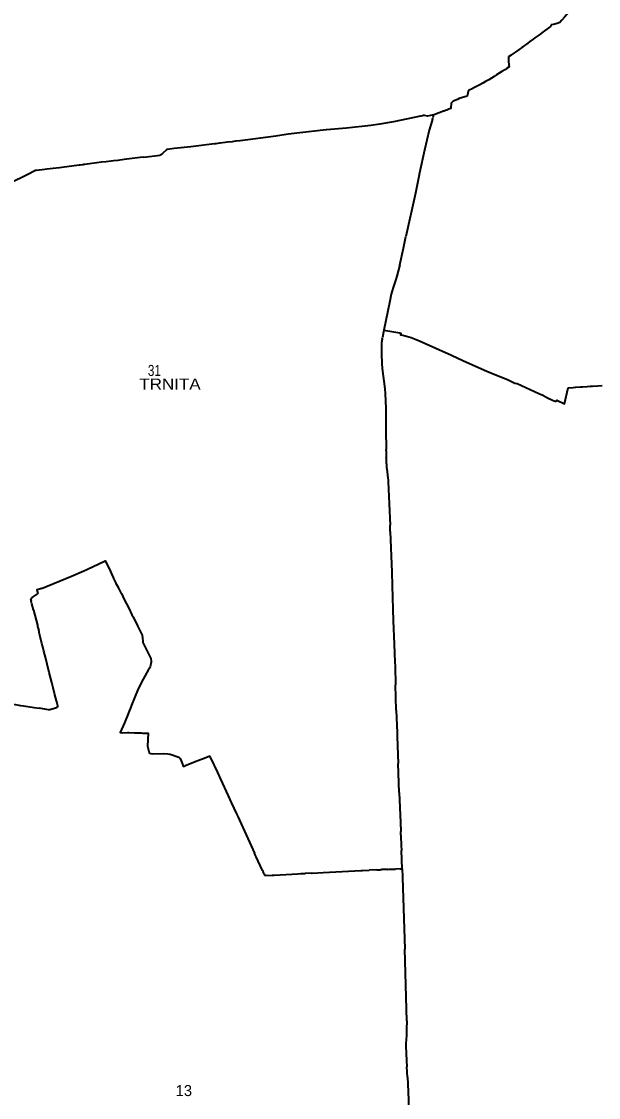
# Model space of a CAD drawing. Extents: x -610940 to -588976, y -1170376 to -1149800.
# Drawn here: x -597562 to -596255, y -1163066 to -1160628 of the extents above; entities that cross this region are included whole.
import ezdxf

# ---------------------------------------------------------------- set-up
doc = ezdxf.new("R2010")
doc.units = 0
doc.header["$LTSCALE"] = 10
doc.layers.add('54', color=7, linetype='Continuous', lineweight=35)
doc.layers.add('55', color=7, linetype='Continuous')
doc.layers.add('56', color=7, linetype='Continuous')

msp = doc.modelspace()

# ---------------------------------------------------------------- linework, layer by layer
at = {"layer": '54'}
for p, q in [((-596361.28, -1160635.63), (-596361.99, -1160635.71)), ((-596342.19, -1160630.16), (-596348.88, -1160632.08)), ((-596549.86, -1160786.62), (-596551.88, -1160794.07)), ((-596549.27, -1160784.45), (-596549.86, -1160786.62)), ((-596653.52, -1160841.44), (-596657.58, -1160842.3)), ((-596651.02, -1160840.91), (-596653.52, -1160841.44)), ((-596649.35, -1160841.13), (-596651.02, -1160840.91)), ((-596629.34, -1160842.41), (-596630.18, -1160846.51)), ((-596628.71, -1160839.33), (-596629.34, -1160842.41)), ((-596630.71, -1160849.11), (-596630.18, -1160846.51)), ((-597095.22, -1160901.65), (-597101.19, -1160902.39)), ((-597344.05, -1160942.66), (-597353.57, -1160943.83)), ((-597329.61, -1160940.82), (-597344.05, -1160942.66)), ((-597285.15, -1160935.22), (-597248.33, -1160930.49)), ((-597246.47, -1160930.25), (-597248.33, -1160930.49)), ((-597242.46, -1160926.68), (-597246.47, -1160930.25)), ((-597430.07, -1160953.25), (-597431.51, -1160953.45)), ((-597429.53, -1160953.19), (-597430.07, -1160953.25)), ((-597422.86, -1160952.37), (-597424.11, -1160952.5)), ((-597380.73, -1160947.01), (-597418.6, -1160951.76)), ((-596669.78, -1161016.63), (-596691.08, -1161114.91)), ((-596704.9, -1161179.49), (-596712.1, -1161204.78)), ((-596741.69, -1161331.15), (-596744.05, -1161344.13)), ((-596741.16, -1161327.91), (-596741.69, -1161331.15)), ((-596741.04, -1161327.3), (-596741.16, -1161327.91)), ((-596744.68, -1161347.37), (-596744.73, -1161347.87)), ((-596744.68, -1161347.37), (-596744.05, -1161344.13)), ((-596736.84, -1161553.27), (-596736, -1161597.69)), ((-596735.95, -1161600.55), (-596736, -1161597.69)), ((-596735.95, -1161600.55), (-596735.93, -1161601.5)), ((-596735.93, -1161601.5), (-596735.66, -1161615.65)), ((-596735.66, -1161615.65), (-596735.64, -1161616.8)), ((-596735.59, -1161619.36), (-596735.64, -1161616.8)), ((-596735.38, -1161630.53), (-596735.59, -1161619.36)), ((-596735.38, -1161630.53), (-596734.96, -1161638.39)), ((-596734.96, -1161638.39), (-596734, -1161646.52)), ((-596734, -1161646.52), (-596732.79, -1161656.86)), ((-596732.79, -1161656.86), (-596731.58, -1161667.09)), ((-596731.58, -1161667.09), (-596731.15, -1161671.05)), ((-596731.15, -1161671.05), (-596729.14, -1161720.69)), ((-596729.14, -1161720.69), (-596726.94, -1161769.42)), ((-596726.66, -1161776.25), (-596726.94, -1161769.42)), ((-596726.61, -1161783.25), (-596726.66, -1161776.25)), ((-597358.38, -1161879.53), (-597354.88, -1161888.15)), ((-597538.25, -1161933.34), (-597542.12, -1161935.99)), ((-597542.12, -1161935.99), (-597540.56, -1161941.62)), ((-597539.06, -1161947.32), (-597540.56, -1161941.62)), ((-597538.25, -1161933.34), (-597528.96, -1161927.14)), ((-597528.96, -1161927.14), (-597528.47, -1161926.81)), ((-597528.47, -1161926.81), (-597527.22, -1161925.96)), ((-597525.1, -1161924.64), (-597527.22, -1161925.96)), ((-597525.1, -1161924.64), (-597525.22, -1161924.16)), ((-597525.77, -1161998.84), (-597523.35, -1162008.25)), ((-597298.72, -1161999.13), (-597298.4, -1161999.66)), ((-597298.02, -1162000.43), (-597298.4, -1161999.66)), ((-596716.06, -1162079.53), (-596715.95, -1162089.1)), ((-596715.95, -1162089.1), (-596714.65, -1162131.42)), ((-596713.28, -1162188.56), (-596714.65, -1162131.42)), ((-597558.11, -1162178.77), (-597533.31, -1162182.49)), ((-597533.31, -1162182.49), (-597522.35, -1162184.25)), ((-597501.5, -1162187.63), (-597522.35, -1162184.25)), ((-597501.5, -1162187.63), (-597481.92, -1162182.56)), ((-597479.8, -1162178.77), (-597481.92, -1162182.56)), ((-596711.1, -1162248.32), (-596708.84, -1162309.27)), ((-597134.47, -1162294.72), (-597126.42, -1162312.09)), ((-596706.41, -1162374.8), (-596708.84, -1162309.27)), ((-597111.13, -1162345.14), (-597094.07, -1162382.32)), ((-596706.41, -1162374.8), (-596703.87, -1162442.68)), ((-597072.18, -1162429.75), (-597034.4, -1162512.2)), ((-596703.87, -1162442.68), (-596703.1, -1162463.36)), ((-596702.78, -1162471.89), (-596703.1, -1162463.36)), ((-596702.03, -1162494.36), (-596701.61, -1162506.82)), ((-597032.55, -1162516.25), (-597034.4, -1162512.2)), ((-597016.3, -1162551.58), (-597030.44, -1162520.85)), ((-596699.58, -1162547.91), (-596701.61, -1162506.82)), ((-597016.3, -1162551.58), (-597014.78, -1162554.89)), ((-596878.48, -1162556.35), (-596792.51, -1162552.05)), ((-596757.26, -1162550.29), (-596774.63, -1162551.16)), ((-596747.82, -1162549.89), (-596746.18, -1162549.82)), ((-596741.73, -1162549.64), (-596746.18, -1162549.82)), ((-596704.56, -1162548.11), (-596701.08, -1162547.97)), ((-597012.75, -1162559.1), (-597014.78, -1162554.89)), ((-597012.75, -1162559.1), (-597010.84, -1162563.09)), ((-596929.62, -1162558.98), (-596919.66, -1162558.45)), ((-596905.17, -1162557.68), (-596919.66, -1162558.45)), ((-596698.99, -1162567.87), (-596693.9, -1162730.32)), ((-596688.82, -1162892.78), (-596693.9, -1162730.32)), ((-596690.16, -1162918.17), (-596690.27, -1162920.56)), ((-596689.27, -1162993.91), (-596689.11, -1162996.91)), ((-596687.89, -1163020.33), (-596689.11, -1162996.91))]:
    msp.add_line(p, q, dxfattribs=at)
for points in [[(-596273.44, -1160540.25), (-596280.42, -1160550.29), (-596285.02, -1160556.87), (-596289.47, -1160563.29), (-596294.15, -1160569.86), (-596298.2, -1160575.35), (-596298.34, -1160575.47), (-596307.24, -1160587.24), (-596307.28, -1160587.47), (-596312.88, -1160594.71), (-596318.4, -1160601.79), (-596322.81, -1160607.17), (-596327.36, -1160612.51), (-596332, -1160618.07), (-596337.97, -1160625.19), (-596342.19, -1160630.16)], [(-596363.49, -1160639.52), (-596376.84, -1160649.22), (-596389.88, -1160658.69), (-596394.39, -1160661.82), (-596398.9, -1160665.06), (-596403.06, -1160668.22), (-596410.31, -1160673.34), (-596415.23, -1160676.89), (-596427.48, -1160685.8), (-596427.33, -1160686.03), (-596431.6, -1160688.94), (-596434.56, -1160691.1)], [(-596363.49, -1160639.52), (-596362.24, -1160637.69), (-596361.99, -1160635.71)], [(-596348.88, -1160632.08), (-596356.69, -1160634.32), (-596361.28, -1160635.63)], [(-596442.11, -1160696.63), (-596446.73, -1160700), (-596446.87, -1160699.81), (-596451.1, -1160702.94), (-596453.08, -1160704.27), (-596458.76, -1160708.19), (-596458.95, -1160719.17), (-596457.08, -1160730.97), (-596463.03, -1160734.71), (-596463.27, -1160734.86), (-596465.86, -1160736.49), (-596473.92, -1160741.47)], [(-596434.56, -1160691.1), (-596439.68, -1160694.85), (-596442.11, -1160696.63)], [(-596473.92, -1160741.47), (-596479.64, -1160745.04), (-596485.69, -1160748.8), (-596491.58, -1160752.5), (-596497.5, -1160756.19), (-596503.44, -1160759.91), (-596510.64, -1160763.95), (-596517.07, -1160767.52), (-596523.55, -1160771.04), (-596529.92, -1160774.55), (-596532.83, -1160775.99), (-596533.05, -1160776.13), (-596537.44, -1160778.4), (-596537.62, -1160778.49), (-596539.2, -1160779.31), (-596539.34, -1160779.4), (-596549.27, -1160784.45)], [(-596551.88, -1160794.07), (-596552.67, -1160796.97), (-596570.65, -1160802.66), (-596574.49, -1160804.27), (-596584.54, -1160808.55), (-596588.55, -1160812.89), (-596589.62, -1160824.14), (-596589.66, -1160824.73), (-596591.97, -1160825.69), (-596594.07, -1160826.58), (-596598.82, -1160828.53)], [(-596657.58, -1160842.3), (-596658.38, -1160842.48), (-596719.45, -1160855.41), (-596750.27, -1160860.4), (-596770.97, -1160863.76), (-596826.22, -1160869.66), (-596871.31, -1160873.02)], [(-596628.71, -1160839.33), (-596642.69, -1160842.03), (-596649.35, -1160841.13)], [(-596598.82, -1160828.53), (-596601.29, -1160829.51), (-596602.89, -1160830.15), (-596605.58, -1160831.19), (-596605.93, -1160831.31), (-596625.66, -1160838.28), (-596628.71, -1160839.33)], [(-596630.71, -1160849.11), (-596632.46, -1160854.62), (-596638.37, -1160874.28), (-596649.21, -1160919.58)], [(-596985.99, -1160887.82), (-597066.88, -1160898.06), (-597067.28, -1160898.11), (-597076.62, -1160899.3), (-597077.47, -1160899.41), (-597085.01, -1160900.36), (-597095.22, -1160901.65)], [(-596871.31, -1160873.02), (-596872.08, -1160873.16), (-596958.3, -1160883), (-596985.99, -1160887.82)], [(-597124.79, -1160905.4), (-597130.84, -1160906.04), (-597178.59, -1160911.56), (-597216.33, -1160915.91), (-597231.99, -1160917.64), (-597233.92, -1160919.06)], [(-597123.81, -1160905.18), (-597124.23, -1160905.27), (-597124.79, -1160905.4)], [(-597122.42, -1160905.11), (-597123.74, -1160905.18), (-597123.81, -1160905.18)], [(-597113.61, -1160903.94), (-597122.33, -1160905.1), (-597122.42, -1160905.11)], [(-597101.19, -1160902.39), (-597112.43, -1160903.79), (-597113.61, -1160903.94)], [(-597285.15, -1160935.22), (-597293.74, -1160936.3), (-597329.61, -1160940.82)], [(-597233.92, -1160919.06), (-597242.16, -1160926.41), (-597242.46, -1160926.68)], [(-596649.21, -1160919.58), (-596660.1, -1160970.96), (-596661.79, -1160978.91), (-596669.78, -1161016.63)], [(-597590.45, -1160994.53), (-597577.12, -1160988.21), (-597560.42, -1160980.25), (-597543.22, -1160971.24), (-597536.36, -1160967.58), (-597532.3, -1160965.69)], [(-597476.58, -1160959.36), (-597504.71, -1160962.66), (-597509.34, -1160963.26), (-597528.56, -1160965.5), (-597532.3, -1160965.69)], [(-597431.51, -1160953.45), (-597470.84, -1160958.68), (-597476.58, -1160959.36)], [(-597424.11, -1160952.5), (-597429.23, -1160953.15), (-597429.53, -1160953.19)], [(-597418.6, -1160951.76), (-597420.83, -1160952.08), (-597422.86, -1160952.37)], [(-597353.57, -1160943.83), (-597370.59, -1160945.89), (-597380.73, -1160947.01)], [(-596704.9, -1161179.49), (-596696.78, -1161141.55), (-596691.08, -1161114.91)], [(-596712.1, -1161204.78), (-596714.44, -1161212.35), (-596720.29, -1161230.91), (-596724.44, -1161246.05), (-596728.04, -1161261.46), (-596741.04, -1161327.3)], [(-596741.04, -1161327.3), (-596731.98, -1161328.97), (-596714.26, -1161332.11), (-596705.03, -1161333.75), (-596702.54, -1161334.46), (-596702.87, -1161334.78), (-596703.35, -1161338.2), (-596701.55, -1161338.23), (-596689.8, -1161341.06), (-596679.19, -1161344.05), (-596667.95, -1161348.36), (-596659.24, -1161352.07), (-596588.24, -1161384.15), (-596560.6, -1161396.67), (-596508.02, -1161420.1), (-596485.72, -1161429.47), (-596461.28, -1161439.53), (-596444.68, -1161447.71), (-596439.34, -1161448.58), (-596389.92, -1161470.85), (-596380.96, -1161475.01), (-596370.62, -1161480.67), (-596359.44, -1161486.25), (-596355.3, -1161487.71), (-596353.09, -1161488.27), (-596351.09, -1161488.44), (-596349.56, -1161486.04), (-596331.58, -1161494.53), (-596323.59, -1161457.84), (-596312.17, -1161457.1), (-596308.04, -1161456.77), (-596306.02, -1161456.62), (-596295.96, -1161455.84), (-596290.88, -1161455.48), (-596280.17, -1161454.72), (-596273.93, -1161454.35), (-596268.35, -1161454), (-596256.72, -1161453.27), (-596246.35, -1161452.65)], [(-596744.73, -1161347.87), (-596746.21, -1161356.03), (-596746.37, -1161381.07), (-596745.69, -1161402.78), (-596744.74, -1161414.35), (-596739.27, -1161460.47), (-596738.61, -1161470.94)], [(-596738.61, -1161470.94), (-596736.51, -1161504.88), (-596736.69, -1161524.12), (-596736.84, -1161553.27)], [(-596726.61, -1161783.25), (-596723.4, -1161875.86), (-596722.33, -1161905.72)], [(-597517.28, -1161913.01), (-597448.65, -1161884.7), (-597421.25, -1161872.96), (-597414.17, -1161869.93), (-597387.09, -1161856.76), (-597386.79, -1161857.17), (-597372.84, -1161850.19), (-597363.22, -1161869.26), (-597358.38, -1161879.53)], [(-597354.88, -1161888.15), (-597353.75, -1161889.76), (-597348.87, -1161900.68)], [(-597517.28, -1161913.01), (-597526.91, -1161915.78), (-597527.28, -1161915.92), (-597525.22, -1161924.16)], [(-597343.83, -1161908.13), (-597344.92, -1161906.51), (-597348.87, -1161900.68)], [(-597336.02, -1161923.91), (-597342.06, -1161911.72), (-597343.83, -1161908.13)], [(-596722.33, -1161905.72), (-596720.01, -1161986.11), (-596717.78, -1162039.3), (-596716.06, -1162079.53)], [(-597336.02, -1161923.91), (-597329.36, -1161937.5), (-597319.47, -1161957.04), (-597312, -1161972.51), (-597309.6, -1161977.35), (-597298.72, -1161999.13)], [(-597535.2, -1161962.02), (-597535.43, -1161961.1), (-597539.06, -1161947.32)], [(-597535.2, -1161962.02), (-597526.44, -1161996.22), (-597525.77, -1161998.84)], [(-597516.67, -1162034.55), (-597520.8, -1162018.57), (-597522.28, -1162012.48), (-597522.61, -1162011.22), (-597523.35, -1162008.25)], [(-597298.02, -1162000.43), (-597288.76, -1162018.65), (-597288.37, -1162025.29), (-597287.64, -1162031.73), (-597287.29, -1162034.8), (-597276.19, -1162057.49), (-597269.53, -1162071.28), (-597269.44, -1162071.87), (-597268.72, -1162076.44), (-597268.58, -1162079.8), (-597271.13, -1162090.53), (-597272.4, -1162093.22), (-597274.27, -1162096.3), (-597283.2, -1162111.65), (-597286.96, -1162118.14), (-597297.95, -1162140.24), (-597299.45, -1162144.1), (-597299.69, -1162143.99), (-597304.9, -1162156.61), (-597304.67, -1162156.66), (-597306.21, -1162160.49), (-597306.53, -1162160.42), (-597313.06, -1162177), (-597312.85, -1162177.03), (-597314.68, -1162181.37), (-597319.99, -1162194.56), (-597320.96, -1162196.92), (-597329.13, -1162216.89), (-597338.37, -1162239.47), (-597334.27, -1162239.52), (-597322.33, -1162239.46), (-597318.93, -1162239.22), (-597306.14, -1162239.86), (-597304.09, -1162239.89), (-597291.25, -1162240.18), (-597288.16, -1162240.29), (-597284.52, -1162240.36), (-597279.62, -1162240.54), (-597275.27, -1162240.6), (-597277.1, -1162270.09)], [(-597513.91, -1162045.29), (-597516.03, -1162037.66), (-597516.67, -1162034.55)], [(-597493.62, -1162125.51), (-597499.33, -1162103.37), (-597504.07, -1162084.57), (-597507.21, -1162071.66), (-597511.52, -1162054.75), (-597513.91, -1162045.29)], [(-597479.8, -1162178.77), (-597482.34, -1162169.89), (-597483.07, -1162167.06), (-597487.3, -1162150.66), (-597490.59, -1162137.69), (-597493.62, -1162125.51)], [(-597580.77, -1162174.72), (-597564.55, -1162177.62), (-597558.11, -1162178.77)], [(-596713.28, -1162188.56), (-596711.4, -1162240.1), (-596711.1, -1162248.32)], [(-597277.1, -1162270.09), (-597272.8, -1162285.07), (-597269.01, -1162286.58), (-597265.22, -1162287.37), (-597241.18, -1162287.05), (-597230.92, -1162287.35), (-597225.63, -1162287.98), (-597205.47, -1162294.78), (-597202.91, -1162298.2), (-597196.92, -1162312.74), (-597196.34, -1162316.31)], [(-597134.47, -1162294.72), (-597135.31, -1162292.87), (-597148.58, -1162298.01), (-597162.72, -1162303.38), (-597191.36, -1162314.29)], [(-597196.34, -1162316.31), (-597193.48, -1162315.07), (-597191.36, -1162314.29)], [(-597126.42, -1162312.09), (-597124.84, -1162315.27), (-597118.28, -1162329.57), (-597111.13, -1162345.14)], [(-597094.07, -1162382.32), (-597087.08, -1162397.41), (-597075.04, -1162423.51), (-597072.18, -1162429.75)], [(-596702.78, -1162471.89), (-596702.68, -1162474.8), (-596702.03, -1162494.36)], [(-597030.44, -1162520.85), (-597030.99, -1162519.65), (-597032.55, -1162516.25)], [(-596792.51, -1162552.05), (-596789.36, -1162551.89), (-596774.63, -1162551.16)], [(-596757.26, -1162550.29), (-596756.03, -1162550.23), (-596755.07, -1162550.18)], [(-596755.07, -1162550.18), (-596750.09, -1162549.98), (-596747.82, -1162549.89)], [(-596732.25, -1162549.23), (-596735.79, -1162549.4), (-596741.73, -1162549.64)], [(-596732.25, -1162549.23), (-596729.35, -1162549.09), (-596720.24, -1162548.67), (-596715.14, -1162548.49)], [(-596704.56, -1162548.11), (-596715.08, -1162548.49), (-596715.14, -1162548.49)], [(-596699.58, -1162547.91), (-596700.58, -1162547.95), (-596701.08, -1162547.97)], [(-596699.58, -1162547.91), (-596699.01, -1162566.51), (-596698.99, -1162567.87)], [(-597010.84, -1162563.09), (-596994.14, -1162562.55), (-596989.65, -1162562.41)], [(-596989.65, -1162562.41), (-596936.36, -1162559.35), (-596929.62, -1162558.98)], [(-596905.17, -1162557.68), (-596904.05, -1162557.58), (-596878.48, -1162556.35)], [(-596688.82, -1162892.78), (-596689.84, -1162911.52), (-596690.16, -1162918.17)], [(-596690.27, -1162920.56), (-596690.08, -1162927.41), (-596690.85, -1162933.32), (-596691.4, -1162945.55), (-596691.56, -1162949.93), (-596690.7, -1162966.42)], [(-596690.7, -1162966.42), (-596690.58, -1162968.78), (-596689.98, -1162980.35), (-596689.71, -1162985.47), (-596689.27, -1162993.91)], [(-596687.89, -1163020.33), (-596686.23, -1163052.33), (-596683.3, -1163135.1), (-596680.9, -1163198.37), (-596679.16, -1163247.31), (-596678.92, -1163268.24), (-596679.09, -1163282.17), (-596678.08, -1163294.51), (-596677.94, -1163295.97), (-596678.27, -1163299.43), (-596678.24, -1163301.44), (-596678.13, -1163303.2), (-596678.04, -1163304.09)]]:
    msp.add_lwpolyline(points, dxfattribs=at)

# ---------------------------------------------------------------- texts
at = {"layer": '55', "width": 1.15}
msp.add_text('TRNITA ', height=25, dxfattribs=at).set_placement((-597295.21, -1161461.99))
at = {"layer": '56', "width": 0.8}
msp.add_text('31 ', height=25, dxfattribs=at).set_placement((-597276.06, -1161431.17))
at = {"layer": '56'}
msp.add_text('13 ', height=25, dxfattribs=at).set_placement((-597213.08, -1163063.03))

doc.saveas('drawing.dxf')
